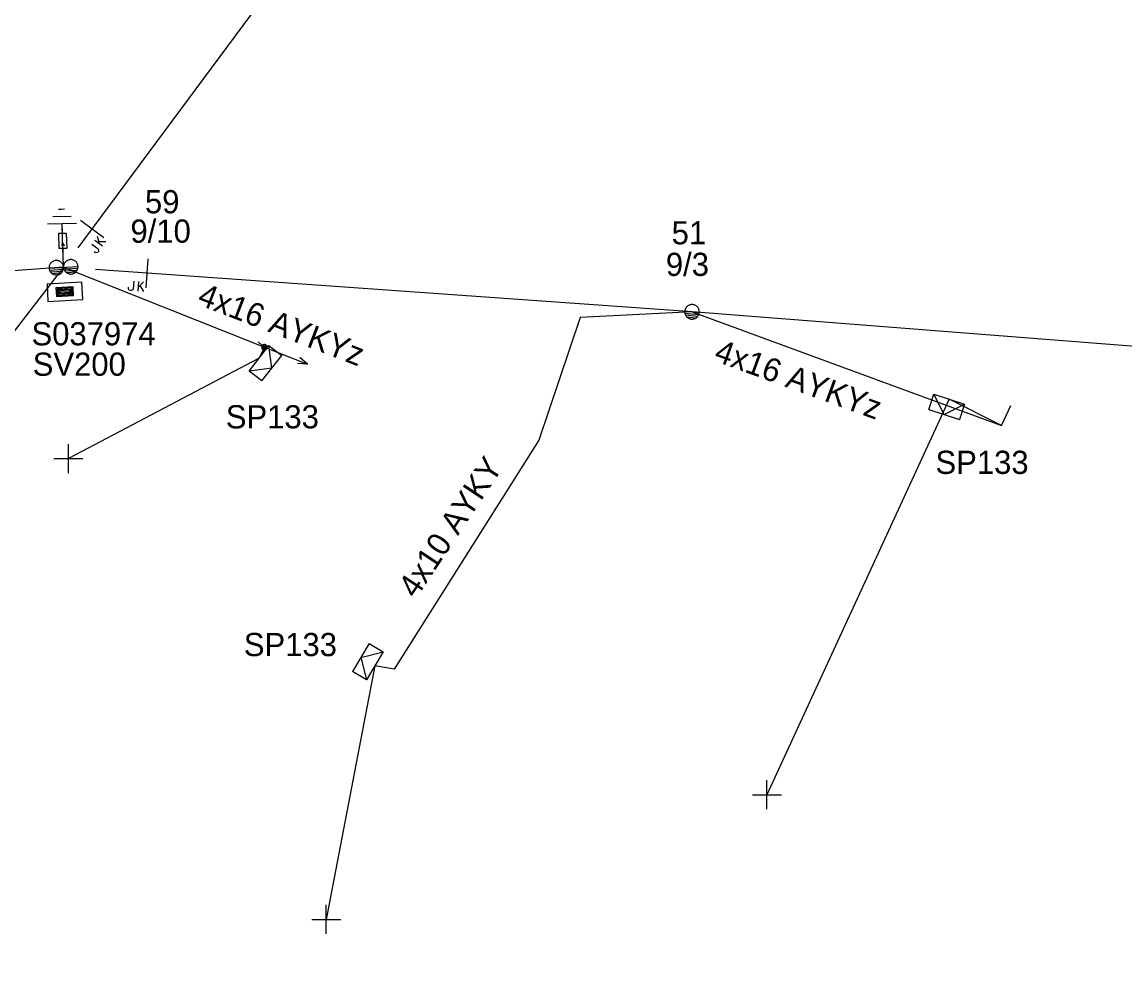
# Model space of a CAD drawing. Extents: x -748492 to -735633, y -1146251 to -1139940.
# Drawn here: x -742472.5 to -742424.94, y -1141302.69 to -1141261.67 of the extents above; entities that cross this region are included whole.
import ezdxf

# ---------------------------------------------------------------- set-up
doc = ezdxf.new("R2010")
doc.units = 0
for name, color, linetype in [('Vrstva 1', 7, 'Continuous'), ('Vrstva 12', 7, 'Continuous'), ('Vrstva 13', 7, 'Continuous'), ('Vrstva 14', 7, 'Continuous'), ('Vrstva 15', 7, 'Continuous'), ('Vrstva 16', 7, 'Continuous'), ('Vrstva 18', 7, 'Continuous'), ('Vrstva 2', 7, 'Continuous'), ('Vrstva 28', 7, 'Continuous'), ('Vrstva 29', 7, 'Continuous'), ('Vrstva 30', 7, 'Continuous'), ('Vrstva 31', 7, 'Continuous'), ('Vrstva 33', 7, 'Continuous'), ('Vrstva 34', 7, 'Continuous'), ('Vrstva 52', 7, 'Continuous'), ('Vrstva 54', 7, 'Continuous'), ('Vrstva 55', 7, 'Continuous'), ('Vrstva 59', 7, 'Continuous'), ('Vrstva 8', 7, 'Continuous'), ('Vrstva 9', 7, 'Continuous')]:
    doc.layers.add(name, color=color, linetype=linetype)

# ---------------------------------------------------------------- blocks, each defined once
blk = doc.blocks.new('NN440')
at = {"layer": 'Vrstva 2'}
for points in [[(0.631, -0.004), (0.627, 0.062), (0.617, 0.127), (0.6, 0.191), (0.577, 0.252), (0.547, 0.311), (0.511, 0.366), (0.469, 0.417), (0.423, 0.464), (0.371, 0.505), (0.316, 0.542), (0.257, 0.571), (0.196, 0.595), (0.132, 0.612), (0.067, 0.622), (0.001, 0.626), (-0.065, 0.622), (-0.13, 0.612), (-0.194, 0.595), (-0.255, 0.571), (-0.314, 0.542), (-0.369, 0.505), (-0.42, 0.464), (-0.467, 0.417), (-0.509, 0.366), (-0.544, 0.311), (-0.574, 0.252), (-0.598, 0.191), (-0.615, 0.127), (-0.626, 0.062), (-0.629, -0.004), (-0.626, -0.07), (-0.615, -0.135), (-0.598, -0.199), (-0.574, -0.26), (-0.544, -0.319), (-0.509, -0.374), (-0.467, -0.426), (-0.42, -0.472), (-0.369, -0.514), (-0.314, -0.55), (-0.255, -0.58), (-0.194, -0.603), (-0.13, -0.62), (-0.065, -0.631), (0.001, -0.634), (0.067, -0.631), (0.132, -0.62), (0.196, -0.603), (0.257, -0.58), (0.316, -0.55), (0.371, -0.514), (0.423, -0.472), (0.469, -0.426), (0.511, -0.374), (0.547, -0.319), (0.577, -0.26), (0.6, -0.199), (0.617, -0.135), (0.627, -0.07), (0.631, -0.004)], [(-0.631, 0), (0.629, 0)], [(-0.601, -0.177), (0.57, -0.177)], [(-0.513, -0.325), (0.501, -0.325)], [(-0.375, -0.473), (0.353, -0.473)]]:
    blk.add_lwpolyline(points, dxfattribs=at)
blk = doc.blocks.new('NN450')
at = {"layer": 'Vrstva 2'}
for points in [[(0, 0), (-0.003, 0.065), (-0.013, 0.13), (-0.031, 0.193), (-0.054, 0.254), (-0.084, 0.312), (-0.119, 0.367), (-0.161, 0.418), (-0.207, 0.464), (-0.258, 0.505), (-0.313, 0.541), (-0.371, 0.571), (-0.432, 0.594), (-0.495, 0.611), (-0.559, 0.621), (-0.625, 0.625), (-0.69, 0.621), (-0.755, 0.611), (-0.818, 0.594), (-0.879, 0.571), (-0.938, 0.541), (-0.992, 0.505), (-1.043, 0.464), (-1.089, 0.418), (-1.13, 0.367), (-1.166, 0.312), (-1.196, 0.254), (-1.219, 0.193), (-1.236, 0.13), (-1.246, 0.065), (-1.25, 0), (-1.246, -0.066), (-1.236, -0.13), (-1.219, -0.193), (-1.196, -0.255), (-1.166, -0.313), (-1.13, -0.368), (-1.089, -0.419), (-1.043, -0.465), (-0.992, -0.506), (-0.937, -0.542), (-0.879, -0.571), (-0.818, -0.595), (-0.755, -0.612), (-0.69, -0.622), (-0.625, -0.625), (-0.559, -0.622), (-0.495, -0.612), (-0.432, -0.595), (-0.37, -0.571), (-0.312, -0.542), (-0.258, -0.506), (-0.207, -0.465), (-0.161, -0.419), (-0.119, -0.368), (-0.084, -0.313), (-0.054, -0.254), (-0.031, -0.193), (-0.013, -0.13), (-0.003, -0.066), (0, 0)], [(1.25, 0), (1.247, 0.065), (1.237, 0.13), (1.219, 0.193), (1.196, 0.254), (1.166, 0.312), (1.131, 0.367), (1.089, 0.418), (1.043, 0.464), (0.992, 0.505), (0.937, 0.541), (0.879, 0.571), (0.818, 0.594), (0.755, 0.611), (0.691, 0.621), (0.625, 0.625), (0.56, 0.621), (0.495, 0.611), (0.432, 0.594), (0.371, 0.571), (0.312, 0.541), (0.258, 0.505), (0.207, 0.464), (0.161, 0.418), (0.12, 0.367), (0.084, 0.312), (0.054, 0.254), (0.031, 0.193), (0.014, 0.13), (0.004, 0.065), (0, 0), (0.004, -0.066), (0.014, -0.13), (0.031, -0.193), (0.054, -0.255), (0.084, -0.313), (0.12, -0.368), (0.161, -0.419), (0.207, -0.465), (0.258, -0.506), (0.313, -0.542), (0.371, -0.571), (0.432, -0.595), (0.495, -0.612), (0.56, -0.622), (0.625, -0.625), (0.691, -0.622), (0.755, -0.612), (0.818, -0.595), (0.88, -0.571), (0.938, -0.542), (0.992, -0.506), (1.043, -0.465), (1.089, -0.419), (1.131, -0.368), (1.166, -0.313), (1.196, -0.254), (1.219, -0.193), (1.237, -0.13), (1.247, -0.066), (1.25, 0)], [(-1.25, 0), (1.25, 0)], [(-1.23, -0.158), (-0.02, -0.158)], [(-1.161, -0.315), (-0.088, -0.315)], [(-1.033, -0.473), (-0.216, -0.473)], [(0.02, -0.158), (1.23, -0.158)], [(0.089, -0.315), (1.162, -0.315)], [(0.217, -0.473), (1.034, -0.473)]]:
    blk.add_lwpolyline(points, dxfattribs=at)
blk = doc.blocks.new('NN560')
at = {"layer": 'Vrstva 2'}
for points in [[(1.999, -0.001), (1.59, 0.141)], [(0, -0.001), (1.999, -0.001)], [(1.999, -0.001), (1.59, -0.134)]]:
    blk.add_lwpolyline(points, dxfattribs=at)
blk = doc.blocks.new('NN840')
at = {"layer": 'Vrstva 15'}
for points in [[(0.003, 0.619), (0.003, -0.631)], [(-0.538, -0.385), (-0.538, -0.71)], [(-0.332, -0.385), (-0.332, -0.798)], [(-0.332, -0.641), (-0.125, -0.385)], [(-0.745, -0.71), (-0.745, -0.66)], [(-0.73, -0.764), (-0.745, -0.71)], [(-0.657, -0.798), (-0.73, -0.764)], [(-0.627, -0.798), (-0.657, -0.798)], [(-0.558, -0.764), (-0.627, -0.798)], [(-0.538, -0.71), (-0.558, -0.764)], [(-0.263, -0.557), (-0.091, -0.798)]]:
    blk.add_lwpolyline(points, dxfattribs=at)
blk = doc.blocks.new('NN800')
at = {"layer": 'Vrstva 1'}
for points in [[(-0.442, 0.442), (0.442, -0.442)], [(-0.442, -0.442), (0.442, 0.442)]]:
    blk.add_lwpolyline(points, dxfattribs=at)
blk = doc.blocks.new('NN820')
at = {"layer": 'Vrstva 13'}
for points in [[(-0.003, 0.004), (-0.003, -1.049)], [(-0.165, -0.813), (0.165, -0.813)], [(-0.165, -1.473), (-0.165, -0.813)], [(-0.003, -1.049), (-0.062, -0.926)], [(-0.003, -1.049), (0.057, -0.926)], [(0.165, -0.813), (0.165, -1.473)], [(0.165, -1.473), (-0.165, -1.473)], [(-0.003, -1.473), (-0.003, -1.871)]]:
    blk.add_lwpolyline(points, dxfattribs=at)
blk = doc.blocks.new('NN620')
at = {"layer": 'Vrstva 8'}
for points in [[(0.752, 0.004), (-0.748, 0.004)], [(-0.748, 0.004), (-0.748, -0.746)], [(0.752, -0.746), (0.752, 0.004)], [(0.368, -0.18), (-0.376, -0.18)], [(-0.376, -0.18), (-0.376, -0.558)], [(0.321, -0.227), (-0.329, -0.227)], [(-0.329, -0.227), (-0.329, -0.51)], [(0.274, -0.274), (-0.281, -0.274)], [(-0.281, -0.274), (-0.281, -0.463)], [(-0.281, -0.463), (0.274, -0.463)], [(0.227, -0.321), (-0.234, -0.321)], [(-0.234, -0.321), (-0.234, -0.416)], [(-0.234, -0.416), (0.227, -0.416)], [(-0.193, -0.369), (0.185, -0.369)], [(0.227, -0.416), (0.227, -0.321)], [(0.274, -0.463), (0.274, -0.274)], [(0.321, -0.51), (0.321, -0.227)], [(0.368, -0.558), (0.368, -0.18)], [(-0.748, -0.746), (0.752, -0.746)], [(-0.376, -0.558), (0.368, -0.558)], [(-0.329, -0.51), (0.321, -0.51)]]:
    blk.add_lwpolyline(points, dxfattribs=at)
blk = doc.blocks.new('NN630')
at = {"layer": 'Vrstva 9'}
for points in [[(-0.003, -0.7), (-0.703, 0)], [(-0.703, -0.7), (-0.703, 0), (0.697, 0), (0.697, -0.7)], [(-0.003, -0.7), (0.697, 0)], [(-0.703, -0.7), (0.697, -0.7)]]:
    blk.add_lwpolyline(points, dxfattribs=at)
blk = doc.blocks.new('NN810')
at = {"layer": 'Vrstva 14'}
for points in [[(0.004, -0.64), (0.004, -1.89)], [(0.629, -1.89), (-0.621, -1.89)], [(0.388, -2.2), (-0.399, -2.2)], [(0.004, -2.515), (-0.124, -2.515)], [(0.137, -2.515), (0.004, -2.515)]]:
    blk.add_lwpolyline(points, dxfattribs=at)
blk = doc.blocks.new('NN500')
at = {"layer": 'Vrstva 2'}
for points in [[(-0.001, -0.235), (0.023, -0.234), (0.048, -0.23), (0.071, -0.224), (0.094, -0.215), (0.116, -0.204), (0.137, -0.191), (0.156, -0.175), (0.173, -0.158), (0.189, -0.139), (0.202, -0.118), (0.213, -0.096), (0.222, -0.073), (0.229, -0.049), (0.232, -0.025), (0.234, 0), (0.232, 0.024), (0.229, 0.048), (0.222, 0.072), (0.213, 0.095), (0.202, 0.117), (0.189, 0.138), (0.173, 0.157), (0.156, 0.174), (0.137, 0.19), (0.116, 0.203), (0.094, 0.214), (0.071, 0.223), (0.048, 0.229), (0.023, 0.233), (-0.001, 0.235), (-0.026, 0.233), (-0.05, 0.229), (-0.074, 0.223), (-0.097, 0.214), (-0.119, 0.203), (-0.139, 0.19), (-0.158, 0.174), (-0.176, 0.157), (-0.191, 0.138), (-0.205, 0.117), (-0.216, 0.095), (-0.225, 0.072), (-0.231, 0.048), (-0.235, 0.024), (-0.236, 0), (-0.235, -0.025), (-0.231, -0.049), (-0.225, -0.073), (-0.216, -0.096), (-0.205, -0.118), (-0.191, -0.139), (-0.176, -0.158), (-0.158, -0.175), (-0.139, -0.191), (-0.119, -0.204), (-0.097, -0.215), (-0.074, -0.224), (-0.05, -0.23), (-0.026, -0.234), (-0.001, -0.235)], [(-0.001, -0.235), (0.023, -0.234), (0.048, -0.23), (0.071, -0.224), (0.094, -0.215), (0.116, -0.204), (0.137, -0.191), (0.156, -0.175), (0.173, -0.158), (0.189, -0.139), (0.202, -0.118), (0.213, -0.096), (0.222, -0.073), (0.229, -0.049), (0.232, -0.025), (0.234, 0), (0.232, 0.024), (0.229, 0.048), (0.222, 0.072), (0.213, 0.095), (0.202, 0.117), (0.189, 0.138), (0.173, 0.157), (0.156, 0.174), (0.137, 0.19), (0.116, 0.203), (0.094, 0.214), (0.071, 0.223), (0.048, 0.229), (0.023, 0.233), (-0.001, 0.235), (-0.026, 0.233), (-0.05, 0.229), (-0.074, 0.223), (-0.097, 0.214), (-0.119, 0.203), (-0.139, 0.19), (-0.158, 0.174), (-0.176, 0.157), (-0.191, 0.138), (-0.205, 0.117), (-0.216, 0.095), (-0.225, 0.072), (-0.231, 0.048), (-0.235, 0.024), (-0.236, 0), (-0.235, -0.025), (-0.231, -0.049), (-0.225, -0.073), (-0.216, -0.096), (-0.205, -0.118), (-0.191, -0.139), (-0.176, -0.158), (-0.158, -0.175), (-0.139, -0.191), (-0.119, -0.204), (-0.097, -0.215), (-0.074, -0.224), (-0.05, -0.23), (-0.026, -0.234), (-0.001, -0.235)], [(-0.001, -0.206), (0.02, -0.205), (0.041, -0.201), (0.062, -0.196), (0.082, -0.188), (0.101, -0.178), (0.12, -0.167), (0.136, -0.153), (0.151, -0.138), (0.165, -0.121), (0.177, -0.103), (0.186, -0.084), (0.194, -0.064), (0.2, -0.043), (0.203, -0.022), (0.204, 0), (0.203, 0.021), (0.2, 0.042), (0.194, 0.063), (0.186, 0.083), (0.177, 0.102), (0.165, 0.12), (0.151, 0.137), (0.136, 0.152), (0.12, 0.166), (0.101, 0.177), (0.082, 0.187), (0.062, 0.195), (0.041, 0.2), (0.02, 0.204), (-0.001, 0.205), (-0.023, 0.204), (-0.044, 0.2), (-0.065, 0.195), (-0.085, 0.187), (-0.104, 0.177), (-0.122, 0.166), (-0.139, 0.152), (-0.154, 0.137), (-0.167, 0.12), (-0.179, 0.102), (-0.189, 0.083), (-0.197, 0.063), (-0.202, 0.042), (-0.205, 0.021), (-0.207, 0), (-0.205, -0.022), (-0.202, -0.043), (-0.197, -0.064), (-0.189, -0.084), (-0.179, -0.103), (-0.167, -0.121), (-0.154, -0.138), (-0.139, -0.153), (-0.122, -0.167), (-0.104, -0.178), (-0.085, -0.188), (-0.065, -0.196), (-0.044, -0.201), (-0.023, -0.205), (-0.001, -0.206)], [(-0.001, -0.176), (0.017, -0.175), (0.035, -0.172), (0.053, -0.168), (0.07, -0.161), (0.087, -0.153), (0.102, -0.143), (0.116, -0.131), (0.129, -0.118), (0.141, -0.104), (0.151, -0.088), (0.159, -0.072), (0.166, -0.055), (0.171, -0.037), (0.174, -0.019), (0.175, 0), (0.174, 0.018), (0.171, 0.036), (0.166, 0.054), (0.159, 0.071), (0.151, 0.087), (0.141, 0.103), (0.129, 0.117), (0.116, 0.13), (0.102, 0.142), (0.087, 0.152), (0.07, 0.16), (0.053, 0.167), (0.035, 0.172), (0.017, 0.174), (-0.001, 0.175), (-0.02, 0.174), (-0.038, 0.172), (-0.056, 0.167), (-0.073, 0.16), (-0.089, 0.152), (-0.105, 0.142), (-0.119, 0.13), (-0.132, 0.117), (-0.143, 0.103), (-0.153, 0.087), (-0.162, 0.071), (-0.168, 0.054), (-0.173, 0.036), (-0.176, 0.018), (-0.177, 0), (-0.176, -0.019), (-0.173, -0.037), (-0.168, -0.055), (-0.162, -0.072), (-0.153, -0.088), (-0.143, -0.104), (-0.132, -0.118), (-0.119, -0.131), (-0.105, -0.143), (-0.089, -0.153), (-0.073, -0.161), (-0.056, -0.168), (-0.038, -0.172), (-0.02, -0.175), (-0.001, -0.176)], [(-0.001, -0.147), (0.014, -0.146), (0.029, -0.143), (0.044, -0.139), (0.058, -0.134), (0.072, -0.127), (0.085, -0.119), (0.097, -0.109), (0.107, -0.098), (0.117, -0.086), (0.125, -0.073), (0.132, -0.06), (0.138, -0.046), (0.142, -0.031), (0.144, -0.016), (0.145, 0), (0.144, 0.015), (0.142, 0.03), (0.138, 0.045), (0.132, 0.059), (0.125, 0.073), (0.117, 0.086), (0.107, 0.097), (0.097, 0.108), (0.085, 0.118), (0.072, 0.126), (0.058, 0.133), (0.044, 0.139), (0.029, 0.143), (0.014, 0.145), (-0.001, 0.146), (-0.017, 0.145), (-0.032, 0.143), (-0.046, 0.139), (-0.061, 0.133), (-0.074, 0.126), (-0.087, 0.118), (-0.099, 0.108), (-0.11, 0.097), (-0.119, 0.086), (-0.128, 0.073), (-0.135, 0.059), (-0.14, 0.045), (-0.144, 0.03), (-0.147, 0.015), (-0.147, 0), (-0.147, -0.016), (-0.144, -0.031), (-0.14, -0.046), (-0.135, -0.06), (-0.128, -0.073), (-0.119, -0.086), (-0.11, -0.098), (-0.099, -0.109), (-0.087, -0.119), (-0.074, -0.127), (-0.061, -0.134), (-0.046, -0.139), (-0.032, -0.143), (-0.017, -0.146), (-0.001, -0.147)], [(-0.001, -0.117), (0.011, -0.116), (0.023, -0.114), (0.035, -0.111), (0.046, -0.107), (0.057, -0.101), (0.067, -0.095), (0.077, -0.087), (0.085, -0.078), (0.093, -0.069), (0.1, -0.059), (0.105, -0.048), (0.11, -0.036), (0.113, -0.025), (0.115, -0.013), (0.115, 0), (0.115, 0.012), (0.113, 0.024), (0.11, 0.036), (0.105, 0.047), (0.1, 0.058), (0.093, 0.068), (0.085, 0.078), (0.077, 0.086), (0.067, 0.094), (0.057, 0.101), (0.046, 0.106), (0.035, 0.11), (0.023, 0.114), (0.011, 0.116), (-0.001, 0.116), (-0.013, 0.116), (-0.025, 0.114), (-0.037, 0.11), (-0.049, 0.106), (-0.059, 0.101), (-0.07, 0.094), (-0.079, 0.086), (-0.088, 0.078), (-0.096, 0.068), (-0.102, 0.058), (-0.108, 0.047), (-0.112, 0.036), (-0.115, 0.024), (-0.117, 0.012), (-0.118, 0), (-0.117, -0.013), (-0.115, -0.025), (-0.112, -0.036), (-0.108, -0.048), (-0.102, -0.059), (-0.096, -0.069), (-0.088, -0.078), (-0.079, -0.087), (-0.07, -0.095), (-0.059, -0.101), (-0.049, -0.107), (-0.037, -0.111), (-0.025, -0.114), (-0.013, -0.116), (-0.001, -0.117)], [(-0.001, -0.087), (0.008, -0.087), (0.017, -0.085), (0.026, -0.083), (0.034, -0.08), (0.042, -0.076), (0.05, -0.071), (0.057, -0.065), (0.063, -0.059), (0.069, -0.051), (0.074, -0.044), (0.078, -0.036), (0.081, -0.027), (0.084, -0.019), (0.085, -0.01), (0.086, 0), (0.085, 0.009), (0.084, 0.018), (0.081, 0.026), (0.078, 0.035), (0.074, 0.043), (0.069, 0.051), (0.063, 0.058), (0.057, 0.064), (0.05, 0.07), (0.042, 0.075), (0.034, 0.079), (0.026, 0.082), (0.017, 0.085), (0.008, 0.086), (-0.001, 0.087), (-0.01, 0.086), (-0.019, 0.085), (-0.028, 0.082), (-0.037, 0.079), (-0.045, 0.075), (-0.052, 0.07), (-0.059, 0.064), (-0.066, 0.058), (-0.072, 0.051), (-0.077, 0.043), (-0.081, 0.035), (-0.084, 0.026), (-0.086, 0.018), (-0.088, 0.009), (-0.088, 0), (-0.088, -0.01), (-0.086, -0.019), (-0.084, -0.027), (-0.081, -0.036), (-0.077, -0.044), (-0.072, -0.052), (-0.066, -0.059), (-0.059, -0.065), (-0.052, -0.071), (-0.045, -0.076), (-0.037, -0.08), (-0.028, -0.083), (-0.019, -0.085), (-0.01, -0.087), (-0.001, -0.087)], [(-0.001, -0.058), (0.005, -0.057), (0.011, -0.056), (0.016, -0.055), (0.022, -0.053), (0.027, -0.05), (0.032, -0.047), (0.037, -0.043), (0.041, -0.039), (0.045, -0.034), (0.048, -0.029), (0.051, -0.024), (0.053, -0.018), (0.055, -0.012), (0.056, -0.006), (0.056, 0), (0.056, 0.006), (0.055, 0.011), (0.053, 0.017), (0.051, 0.023), (0.048, 0.028), (0.045, 0.033), (0.041, 0.038), (0.037, 0.042), (0.032, 0.046), (0.027, 0.049), (0.022, 0.052), (0.016, 0.054), (0.011, 0.056), (0.005, 0.057), (-0.001, 0.057), (-0.007, 0.057), (-0.013, 0.056), (-0.019, 0.054), (-0.025, 0.052), (-0.03, 0.049), (-0.035, 0.046), (-0.04, 0.042), (-0.044, 0.038), (-0.048, 0.033), (-0.051, 0.028), (-0.054, 0.023), (-0.056, 0.017), (-0.057, 0.011), (-0.058, 0.006), (-0.059, 0), (-0.058, -0.006), (-0.057, -0.012), (-0.056, -0.018), (-0.054, -0.024), (-0.051, -0.029), (-0.048, -0.034), (-0.044, -0.039), (-0.04, -0.043), (-0.035, -0.047), (-0.03, -0.05), (-0.025, -0.053), (-0.019, -0.055), (-0.013, -0.056), (-0.007, -0.057), (-0.001, -0.058)], [(-0.001, -0.028), (0.002, -0.028), (0.005, -0.028), (0.007, -0.027), (0.01, -0.026), (0.013, -0.024), (0.015, -0.023), (0.017, -0.021), (0.019, -0.019), (0.021, -0.017), (0.023, -0.014), (0.024, -0.012), (0.025, -0.009), (0.026, -0.006), (0.026, -0.003), (0.027, 0), (0.026, 0.002), (0.026, 0.005), (0.025, 0.008), (0.024, 0.011), (0.023, 0.013), (0.021, 0.016), (0.019, 0.018), (0.017, 0.02), (0.015, 0.022), (0.013, 0.024), (0.01, 0.025), (0.007, 0.026), (0.005, 0.027), (0.002, 0.027), (-0.001, 0.027), (-0.004, 0.027), (-0.007, 0.027), (-0.01, 0.026), (-0.012, 0.025), (-0.015, 0.024), (-0.018, 0.022), (-0.02, 0.02), (-0.022, 0.018), (-0.024, 0.016), (-0.025, 0.013), (-0.027, 0.011), (-0.028, 0.008), (-0.028, 0.005), (-0.029, 0.002), (-0.029, 0), (-0.029, -0.003), (-0.028, -0.006), (-0.028, -0.009), (-0.027, -0.012), (-0.025, -0.014), (-0.024, -0.017), (-0.022, -0.019), (-0.02, -0.021), (-0.018, -0.023), (-0.015, -0.024), (-0.012, -0.026), (-0.01, -0.027), (-0.007, -0.028), (-0.004, -0.028), (-0.001, -0.028)], [(0.234, 0), (0.704, 0)]]:
    blk.add_lwpolyline(points, dxfattribs=at)
blk = doc.blocks.new('NN510')
at = {"layer": 'Vrstva 2'}
blk.add_lwpolyline([(0.001, 0.002), (0.001, 0.939)], dxfattribs=at)

msp = doc.modelspace()

# ---------------------------------------------------------------- linework, layer by layer
at = {"layer": 'Vrstva 1'}
for points in [[(-742256.596, -1141175.41), (-742282.97, -1141171.66), (-742315.22, -1141163.23), (-742347.84, -1141166.52), (-742383.69, -1141173.21), (-742409.32, -1141200.59), (-742434.14, -1141226.78), (-742453.46, -1141248.98), (-742470.088, -1141271.411)], [(-742299.67, -1141262.36), (-742331.74, -1141266.81), (-742371.35, -1141272.49), (-742405.38, -1141277.16), (-742443.61, -1141274.17), (-742469.334, -1141272.347)], [(-742470.71, -1141272.25), (-742490.66, -1141273.69), (-742512.85, -1141288.6), (-742537.76, -1141302.69)]]:
    msp.add_lwpolyline(points, dxfattribs=at)
at = {"layer": 'Vrstva 52'}
msp.add_lwpolyline([(-742443.61, -1141274.17), (-742448.44, -1141274.42), (-742450.22, -1141279.71), (-742456.46, -1141289.58), (-742457.29, -1141289.44)], dxfattribs=at)
at = {"layer": 'Vrstva 54'}
for points in [[(-742470.71, -1141272.25), (-742487.8, -1141294.4), (-742488.02, -1141294.55)], [(-742470.71, -1141272.25), (-742462.051, -1141275.699), (-742462.28, -1141276.17)], [(-742443.61, -1141274.17), (-742430.26, -1141279.07), (-742432.52, -1141277.94)]]:
    msp.add_lwpolyline(points, dxfattribs=at)
at = {"layer": 'Vrstva 59'}
for points in [[(-742462.28, -1141276.17), (-742470.5, -1141280.5)], [(-742432.52, -1141277.94), (-742440.38, -1141295)], [(-742457.29, -1141289.44), (-742459.38, -1141300.38)]]:
    msp.add_lwpolyline(points, dxfattribs=at)

# ---------------------------------------------------------------- block references
at = {"layer": 'Vrstva 13'}
for name, p, xscale, yscale, rotation in [('NN450', (-742470.71, -1141272.25), 0.5000000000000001, 0.5, 3.7679108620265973), ('NN440', (-742443.61, -1141274.17), 0.5000000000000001, 0.5, -5.949360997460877), ('NN500', (-742462.05, -1141275.7), 0.5, 0.5000000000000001, 139.2558939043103)]:
    msp.add_blockref(name, p, dxfattribs=dict(at, xscale=xscale, yscale=yscale, rotation=rotation))
for name, p, rotation in [('NN560', (-742462.051, -1141275.699), -21.311331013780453), ('NN510', (-742430.26, -1141279.07), -24.654038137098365)]:
    msp.add_blockref(name, p, dxfattribs=dict(at, rotation=rotation))
at = {"layer": 'Vrstva 15', "rotation": -178.12957962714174}
msp.add_blockref('NN810', (-742470.71, -1141272.25), dxfattribs=at)
at = {"layer": 'Vrstva 16', "rotation": -178.23201362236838}
msp.add_blockref('NN820', (-742470.71, -1141272.25), dxfattribs=at)
at = {"layer": 'Vrstva 18'}
for p, rotation in [((-742469.478, -1141270.588), 53.450540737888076), ((-742467.116, -1141272.505), -4.052560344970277)]:
    msp.add_blockref('NN840', p, dxfattribs=dict(at, rotation=rotation))
at = {"layer": 'Vrstva 28', "rotation": 3.19953958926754}
msp.add_blockref('NN620', (-742470.676, -1141272.934), dxfattribs=at)
at = {"layer": 'Vrstva 31'}
for p, rotation in [((-742462.28, -1141276.17), 52.0643230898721), ((-742432.52, -1141277.94), -17.807635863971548), ((-742457.29, -1141289.44), -120.43327302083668)]:
    msp.add_blockref('NN630', p, dxfattribs=dict(at, rotation=rotation))
at = {"layer": 'Vrstva 34', "rotation": 45}
for p in [(-742470.5, -1141280.5), (-742440.38, -1141295), (-742459.38, -1141300.38)]:
    msp.add_blockref('NN800', p, dxfattribs=at)

# ---------------------------------------------------------------- texts
at = {"layer": 'Vrstva 12'}
for s, rotation, p in [('9/10', 0.041, (-742467.824, -1141271.19)), ('9/3', 0.048, (-742444.738, -1141272.624))]:
    msp.add_text(s, height=1, rotation=rotation, dxfattribs=at).set_placement(p)
at = {"layer": 'Vrstva 14'}
for s, rotation, p in [('59', 0.019, (-742467.2, -1141269.921)), ('51', 0.035, (-742444.489, -1141271.261))]:
    msp.add_text(s, height=1, rotation=rotation, dxfattribs=at).set_placement(p)
at = {"layer": 'Vrstva 29'}
msp.add_text('S037974', height=1, rotation=359.989, dxfattribs=at).set_placement((-742472.092, -1141275.618))
at = {"layer": 'Vrstva 30'}
msp.add_text('SV200', height=1, rotation=0.042, dxfattribs=at).set_placement((-742472.04, -1141276.931))
at = {"layer": 'Vrstva 33'}
msp.add_text('SP133', height=1, dxfattribs=at).set_placement((-742463.714, -1141279.198))
for rotation, p in [(359.992, (-742433.112, -1141281.163)), (359.982, (-742462.937, -1141289.023))]:
    msp.add_text('SP133', height=1, rotation=rotation, dxfattribs=at).set_placement(p)
at = {"layer": 'Vrstva 54'}
msp.add_text('4x10 AYKY', height=1, rotation=56.461, dxfattribs=at).set_placement((-742455.513, -1141286.573))
at = {"layer": 'Vrstva 55'}
for rotation, p in [(338.915, (-742464.992, -1141273.833)), (339.998, (-742442.713, -1141276.268))]:
    msp.add_text('4x16 AYKYz', height=1, rotation=rotation, dxfattribs=at).set_placement(p)

doc.saveas('drawing.dxf')
